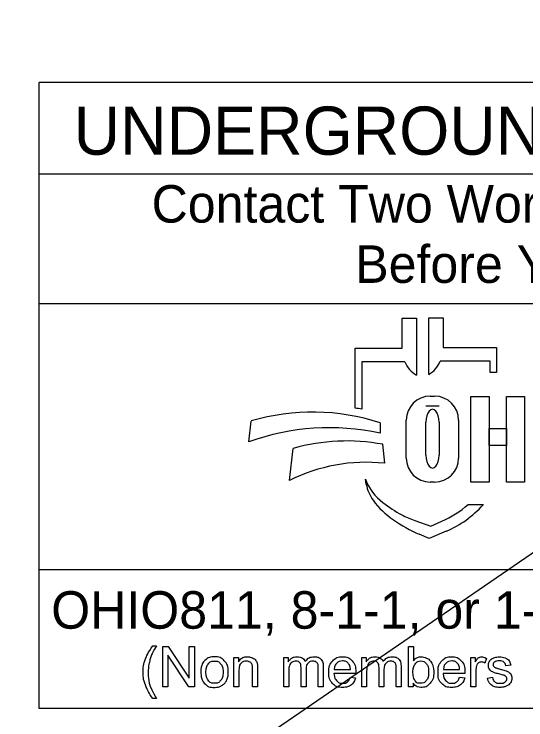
# Model space of a CAD drawing. Extents: x -1.8 to 75.7, y -2 to 25.
# Drawn here: x 2.883 to 4.796, y 2.1 to 4.736 of the extents above; entities that cross this region are included whole.
import ezdxf

# ---------------------------------------------------------------- set-up
doc = ezdxf.new("R2010")
doc.units = 0
for name, color, linetype in [('SH_Data', 7, 'Continuous'), ('SH_Text', 7, 'Continuous'), ('TX_P_1', 7, 'Continuous')]:
    doc.layers.add(name, color=color, linetype=linetype)

msp = doc.modelspace()

# ---------------------------------------------------------------- linework, layer by layer
at = {"layer": 'SH_Data'}
for p, q in [((2.9775, 2.1428), (2.9775, 4.4803)), ((7.2275, 4.4803), (2.9775, 4.4803)), ((2.9775, 4.1387), (7.2275, 4.1387)), ((2.9775, 3.6553), (7.2275, 3.6553)), ((7.2275, 2.6607), (2.9775, 2.6607)), ((7.2275, 2.1428), (2.9775, 2.1428))]:
    msp.add_line(p, q, dxfattribs=at)
at = {"layer": 'SH_Text'}
for p, q in [((4.3335, 3.4883), (4.3335, 3.5998)), ((4.3335, 3.5998), (4.3872, 3.5998)), ((4.3872, 3.5998), (4.3872, 3.3877)), ((4.4329, 3.39), (4.4329, 3.6021)), ((4.4329, 3.6021), (4.4865, 3.6021)), ((4.4865, 3.6021), (4.4865, 3.4906)), ((4.1576, 3.2644), (4.1576, 3.4883)), ((4.1576, 3.4883), (4.3335, 3.4883)), ((4.4865, 3.4906), (4.6857, 3.4906)), ((4.6857, 3.4906), (4.6857, 3.3968)), ((4.1828, 3.4369), (4.1828, 3.26)), ((4.3439, 3.4369), (4.1828, 3.4369)), ((4.6625, 3.4392), (4.4761, 3.4392)), ((4.6625, 3.3968), (4.6625, 3.4392)), ((4.6857, 3.3968), (4.6625, 3.3968)), ((4.4385, 3.3091), (4.4551, 3.3091)), ((4.4718, 3.2721), (4.422, 3.2721)), ((3.7602, 3.1381), (3.7696, 3.2162)), ((4.3491, 3.0776), (4.3491, 3.2196)), ((4.5445, 3.2196), (4.5445, 3.0776)), ((4.2509, 3.2097), (4.2509, 3.1709)), ((4.422, 3.089), (4.422, 3.2114)), ((4.4718, 3.2114), (4.4718, 3.089)), ((3.912, 2.9936), (3.9267, 3.1137)), ((4.2608, 3.1291), (4.2671, 3.0582)), ((4.1997, 2.9807), (4.1967, 2.9986)), ((4.4551, 2.9882), (4.4385, 2.9882)), ((4.58, 2.9048), (4.6375, 2.9048)), ((4.3816, 2.8444), (4.441, 2.8239)), ((4.441, 2.8239), (4.4821, 2.8417)), ((4.4983, 2.8044), (4.435, 2.7769)), ((4.435, 2.7769), (4.3976, 2.7934))]:
    msp.add_line(p, q, dxfattribs=at)
for points in [[(4.591, 3.3081), (4.6589, 3.3081), (4.6589, 2.9881), (4.591, 2.9881)], [(4.7231, 3.3081), (4.7911, 3.3081), (4.7911, 2.9881), (4.7231, 2.9881)], [(4.6589, 3.1882), (4.7231, 3.1882), (4.7231, 3.1242), (4.6589, 3.1242)]]:
    msp.add_lwpolyline(points, close=True, dxfattribs=at)
for points in [[(3.4021, 2.3766), (3.4153, 2.3766)], [(3.4389, 2.2239), (3.4389, 2.3741), (3.4592, 2.3741), (3.5382, 2.2561), (3.5382, 2.3741), (3.5572, 2.3741), (3.5572, 2.2239), (3.5369, 2.2239), (3.4579, 2.3419), (3.4579, 2.2239), (3.4389, 2.2239)], [(4.3743, 2.2239), (4.3573, 2.2239), (4.3573, 2.3741), (4.3757, 2.3741), (4.3757, 2.3206)], [(3.7048, 2.2239), (3.7048, 2.3328), (3.7214, 2.3328), (3.7214, 2.3173)], [(3.8912, 2.2239), (3.8912, 2.3328), (3.9077, 2.3328), (3.9077, 2.3174)], [(4.1826, 2.2239), (4.1826, 2.3328), (4.1991, 2.3328), (4.1991, 2.3174)], [(4.5904, 2.2239), (4.5904, 2.3328), (4.607, 2.3328), (4.607, 2.3163)], [(4.6495, 2.3293), (4.643, 2.3122)], [(3.9743, 2.2871), (3.9743, 2.2239), (3.9559, 2.2239), (3.9559, 2.2946)], [(4.0388, 2.2986), (4.0388, 2.2239), (4.0203, 2.2239), (4.0203, 2.2924)], [(4.2657, 2.2871), (4.2657, 2.2239), (4.2473, 2.2239), (4.2473, 2.2946)], [(4.3301, 2.2986), (4.3301, 2.2239), (4.3117, 2.2239), (4.3117, 2.2924)], [(4.7394, 2.3046), (4.7213, 2.3022)], [(3.7233, 2.2833), (3.7233, 2.2239), (3.7048, 2.2239)], [(3.7932, 2.2908), (3.7932, 2.2239), (3.7748, 2.2239), (3.7748, 2.2901)], [(3.9097, 2.2803), (3.9097, 2.2239), (3.8912, 2.2239)], [(4.16, 2.2736), (4.0788, 2.2736)], [(4.0799, 2.2887), (4.1406, 2.2887)], [(4.201, 2.2803), (4.201, 2.2239), (4.1826, 2.2239)], [(4.568, 2.2736), (4.4868, 2.2736)], [(4.4879, 2.2887), (4.5486, 2.2887)], [(4.6088, 2.2809), (4.6088, 2.2239), (4.5904, 2.2239)], [(4.1404, 2.2591), (4.1595, 2.2567)], [(4.5484, 2.2591), (4.5675, 2.2567)], [(4.653, 2.2564), (4.6712, 2.2593)], [(4.3743, 2.2375), (4.3743, 2.2239)], [(3.4153, 2.1798), (3.4021, 2.1798)]]:
    msp.add_lwpolyline(points, dxfattribs=at)
for centre, radius, start, end in [((4.4353, 3.4736), 0.0985, 201.9296, 240.7469), ((4.3847, 3.476), 0.0985, 299.2531, 338.0704), ((4.4385, 3.2196), 0.0895, 90, 180), ((4.4551, 3.2196), 0.0895, 0, 90), ((3.9997, 2.4302), 0.8191, 72.1402, 106.3144), ((4.0295, 2.4554), 0.8191, 79.2074, 81.0007), ((4.0628, 2.2991), 0.8919, 77.8238, 109.8274), ((4.1267, 2.4094), 0.7322, 79.44, 105.8467), ((4.1987, 2.4262), 0.6357, 83.8248, 116.8021), ((4.4385, 3.0776), 0.0895, 180, 270), ((4.4551, 3.0776), 0.0895, 270, 0), ((4.3841, 3.0707), 0.2008, 201.0457, 232.5314), ((4.341, 3.0048), 0.1433, 189.6817, 216.0884), ((4.4747, 3.1022), 0.3088, 216.0884, 235.7167), ((4.5766, 3.3219), 0.5173, 232.5314, 241.794), ((4.3387, 3.1722), 0.3602, 293.4582, 312.0712), ((4.3387, 3.1722), 0.401, 293.4582, 317.8286), ((4.6412, 3.3465), 0.6044, 235.7167, 246.2325), ((4.4914, 3.1631), 0.3371, 241.794, 250.9821)]:
    msp.add_arc(centre, radius, start, end, dxfattribs=at)
for centre, start_param, end_param in [((4.4469, 3.2114), 4.712389, 7.853982), ((4.4469, 3.089), 1.570796, 4.712389)]:
    msp.add_ellipse(centre, major_axis=(0, 0.0484), ratio=0.514403, start_param=start_param, end_param=end_param, dxfattribs=at)
for points in [[(3.4021, 2.1798), (3.3869, 2.199), (3.3763, 2.2248), (3.3657, 2.2506), (3.3657, 2.2783), (3.3657, 2.3026), (3.3736, 2.325), (3.3829, 2.3509), (3.4021, 2.3766)], [(3.4153, 2.3766), (3.4029, 2.3553), (3.3989, 2.3462), (3.3927, 2.332), (3.3891, 2.3167), (3.3847, 2.2975), (3.3847, 2.2782), (3.3847, 2.2289), (3.4153, 2.1798)], [(3.5814, 2.2783), (3.5814, 2.3085), (3.5981, 2.3231), (3.6122, 2.3352), (3.6323, 2.3352), (3.6547, 2.3352), (3.669, 2.3205), (3.6832, 2.3058), (3.6832, 2.2799), (3.6832, 2.2589), (3.6769, 2.2469), (3.6706, 2.2348), (3.6586, 2.2282), (3.6466, 2.2215), (3.6323, 2.2215), (3.6095, 2.2215), (3.5954, 2.2362), (3.5814, 2.2508), (3.5814, 2.2783)], [(3.6003, 2.2783), (3.6003, 2.2574), (3.6094, 2.247), (3.6185, 2.2366), (3.6323, 2.2366), (3.646, 2.2366), (3.6551, 2.2471), (3.6642, 2.2575), (3.6642, 2.279), (3.6642, 2.2991), (3.6551, 2.3095), (3.6459, 2.3199), (3.6323, 2.3199), (3.6185, 2.3199), (3.6094, 2.3096), (3.6003, 2.2992), (3.6003, 2.2783)], [(3.7214, 2.3173), (3.7334, 2.3352), (3.756, 2.3352), (3.7659, 2.3352), (3.7741, 2.3316), (3.7823, 2.3281), (3.7864, 2.3224), (3.7905, 2.3166), (3.7922, 2.3087), (3.7932, 2.3036), (3.7932, 2.2908)], [(3.9077, 2.3174), (3.9128, 2.3254), (3.9214, 2.3303), (3.9299, 2.3352), (3.9407, 2.3352), (3.9528, 2.3352), (3.9606, 2.3301), (3.9683, 2.3251), (3.9715, 2.3161), (3.9844, 2.3352), (4.0051, 2.3352), (4.0213, 2.3352), (4.03, 2.3262), (4.0388, 2.3172), (4.0388, 2.2986)], [(4.1595, 2.2567), (4.155, 2.24), (4.1428, 2.2307), (4.1306, 2.2215), (4.1117, 2.2215), (4.0878, 2.2215), (4.0738, 2.2362), (4.0598, 2.2509), (4.0598, 2.2774), (4.0598, 2.3049), (4.074, 2.32), (4.0881, 2.3352), (4.1106, 2.3352), (4.1324, 2.3352), (4.1463, 2.3203), (4.1601, 2.3055), (4.1601, 2.2785), (4.1601, 2.2769), (4.16, 2.2736)], [(4.1406, 2.2887), (4.1394, 2.3025), (4.1337, 2.3094), (4.1249, 2.3201), (4.1108, 2.3201), (4.0981, 2.3201), (4.0894, 2.3115), (4.0808, 2.303), (4.0799, 2.2887)], [(4.1991, 2.3174), (4.2042, 2.3254), (4.2127, 2.3303), (4.2212, 2.3352), (4.2321, 2.3352), (4.2442, 2.3352), (4.2519, 2.3301), (4.2597, 2.3251), (4.2628, 2.3161), (4.2758, 2.3352), (4.2965, 2.3352), (4.3127, 2.3352), (4.3214, 2.3262), (4.3301, 2.3172), (4.3301, 2.2986)], [(4.3741, 2.2792), (4.3741, 2.2596), (4.3794, 2.2509), (4.3881, 2.2366), (4.4029, 2.2366), (4.415, 2.2366), (4.4238, 2.2471), (4.4326, 2.2576), (4.4326, 2.2784), (4.4326, 2.2998), (4.4241, 2.3099), (4.4157, 2.3201), (4.4038, 2.3201), (4.3917, 2.3201), (4.3829, 2.3096), (4.3741, 2.299), (4.3741, 2.2792)], [(4.3757, 2.3206), (4.3874, 2.3352), (4.4055, 2.3352), (4.4155, 2.3352), (4.4245, 2.3311), (4.4335, 2.3271), (4.4392, 2.3198), (4.445, 2.3124), (4.4483, 2.3021), (4.4516, 2.2918), (4.4516, 2.28), (4.4516, 2.252), (4.4378, 2.2368), (4.4239, 2.2215), (4.4046, 2.2215), (4.3853, 2.2215), (4.3743, 2.2375)], [(4.5675, 2.2567), (4.563, 2.24), (4.5508, 2.2307), (4.5386, 2.2215), (4.5196, 2.2215), (4.4958, 2.2215), (4.4818, 2.2362), (4.4678, 2.2509), (4.4678, 2.2774), (4.4678, 2.3049), (4.482, 2.32), (4.4961, 2.3352), (4.5186, 2.3352), (4.5404, 2.3352), (4.5543, 2.3203), (4.5681, 2.3055), (4.5681, 2.2785), (4.5681, 2.2769), (4.568, 2.2736)], [(4.5486, 2.2887), (4.5474, 2.3025), (4.5417, 2.3094), (4.5328, 2.3201), (4.5188, 2.3201), (4.5061, 2.3201), (4.4974, 2.3115), (4.4888, 2.303), (4.4879, 2.2887)], [(4.607, 2.3163), (4.6133, 2.3278), (4.6187, 2.3315), (4.6241, 2.3352), (4.6305, 2.3352), (4.6398, 2.3352), (4.6495, 2.3293)], [(4.7213, 2.3022), (4.7201, 2.3106), (4.7142, 2.3153), (4.7083, 2.3201), (4.6975, 2.3201), (4.6848, 2.3201), (4.6794, 2.3159), (4.6739, 2.3116), (4.6739, 2.306), (4.6739, 2.3024), (4.6762, 2.2995), (4.6785, 2.2966), (4.6833, 2.2946), (4.686, 2.2936), (4.6996, 2.2899), (4.7192, 2.2847), (4.7269, 2.2813), (4.7347, 2.278), (4.7391, 2.2717), (4.7435, 2.2653), (4.7435, 2.2559), (4.7435, 2.2467), (4.7381, 2.2386), (4.7327, 2.2304), (4.7226, 2.226), (4.7124, 2.2215), (4.6996, 2.2215), (4.6784, 2.2215), (4.6672, 2.2303), (4.6561, 2.2391), (4.653, 2.2564)], [(4.6712, 2.2593), (4.6727, 2.2483), (4.6798, 2.2425), (4.6868, 2.2366), (4.6995, 2.2366), (4.7122, 2.2366), (4.7184, 2.2418), (4.7245, 2.247), (4.7245, 2.254), (4.7245, 2.2602), (4.7191, 2.2638), (4.7153, 2.2663), (4.7002, 2.2701), (4.6799, 2.2752), (4.672, 2.2789), (4.6642, 2.2827), (4.6601, 2.2893), (4.6561, 2.2959), (4.6561, 2.3038), (4.6561, 2.3111), (4.6594, 2.3173), (4.6628, 2.3235), (4.6685, 2.3276), (4.6728, 2.3308), (4.6803, 2.333), (4.6877, 2.3352), (4.6962, 2.3352), (4.709, 2.3352), (4.7187, 2.3315), (4.7284, 2.3278), (4.733, 2.3215), (4.7377, 2.3152), (4.7394, 2.3046)], [(3.7748, 2.2901), (3.7748, 2.3013), (3.7726, 2.3069), (3.7705, 2.3125), (3.765, 2.3158), (3.7595, 2.3191), (3.7521, 2.3191), (3.7404, 2.3191), (3.7318, 2.3117), (3.7233, 2.3042), (3.7233, 2.2833)], [(3.9559, 2.2946), (3.9559, 2.3069), (3.9514, 2.313), (3.9469, 2.3191), (3.9366, 2.3191), (3.9288, 2.3191), (3.9222, 2.315), (3.9156, 2.311), (3.9126, 2.3031), (3.9097, 2.2952), (3.9097, 2.2803)], [(4.0203, 2.2924), (4.0203, 2.3035), (4.0185, 2.3083), (4.0168, 2.3132), (4.012, 2.3162), (4.0073, 2.3191), (4.001, 2.3191), (3.9895, 2.3191), (3.9819, 2.3115), (3.9743, 2.3039), (3.9743, 2.2871)], [(4.2473, 2.2946), (4.2473, 2.3069), (4.2428, 2.313), (4.2383, 2.3191), (4.228, 2.3191), (4.2202, 2.3191), (4.2136, 2.315), (4.207, 2.311), (4.204, 2.3031), (4.201, 2.2952), (4.201, 2.2803)], [(4.3117, 2.2924), (4.3117, 2.3035), (4.3099, 2.3083), (4.3081, 2.3132), (4.3034, 2.3162), (4.2987, 2.3191), (4.2923, 2.3191), (4.2809, 2.3191), (4.2733, 2.3115), (4.2657, 2.3039), (4.2657, 2.2871)], [(4.643, 2.3122), (4.6363, 2.3162), (4.6295, 2.3162), (4.6235, 2.3162), (4.6187, 2.3125), (4.6139, 2.3089), (4.6119, 2.3024), (4.6088, 2.2926), (4.6088, 2.2809)], [(4.0788, 2.2736), (4.0799, 2.2557), (4.089, 2.2462), (4.0981, 2.2366), (4.1117, 2.2366), (4.1219, 2.2366), (4.1291, 2.242), (4.1362, 2.2473), (4.1404, 2.2591)], [(4.4868, 2.2736), (4.4879, 2.2557), (4.497, 2.2462), (4.5061, 2.2366), (4.5197, 2.2366), (4.5299, 2.2366), (4.537, 2.242), (4.5442, 2.2473), (4.5484, 2.2591)]]:
    msp.add_open_spline(points, degree=3, dxfattribs=at)
at = {"layer": 'TX_P_1'}
msp.add_line((37.3674, 24.9928), (-1.7055, -1.7436), dxfattribs=at)

# ---------------------------------------------------------------- texts
at = {"layer": 'SH_Text'}
for s, height, p in [('UNDERGROUND UTILITIES', 0.18, (3.1057, 4.2106)), ('Contact Two Working Days', 0.14, (3.3972, 3.9571)), ('Before You Dig', 0.14, (4.1583, 3.7321)), ('OHIO811, 8-1-1, or 1-800-362-2764', 0.14, (3.022, 2.4406))]:
    msp.add_text(s, height=height, dxfattribs=at).set_placement(p)

doc.saveas('drawing.dxf')
